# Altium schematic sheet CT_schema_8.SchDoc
size 368 x 245 mm
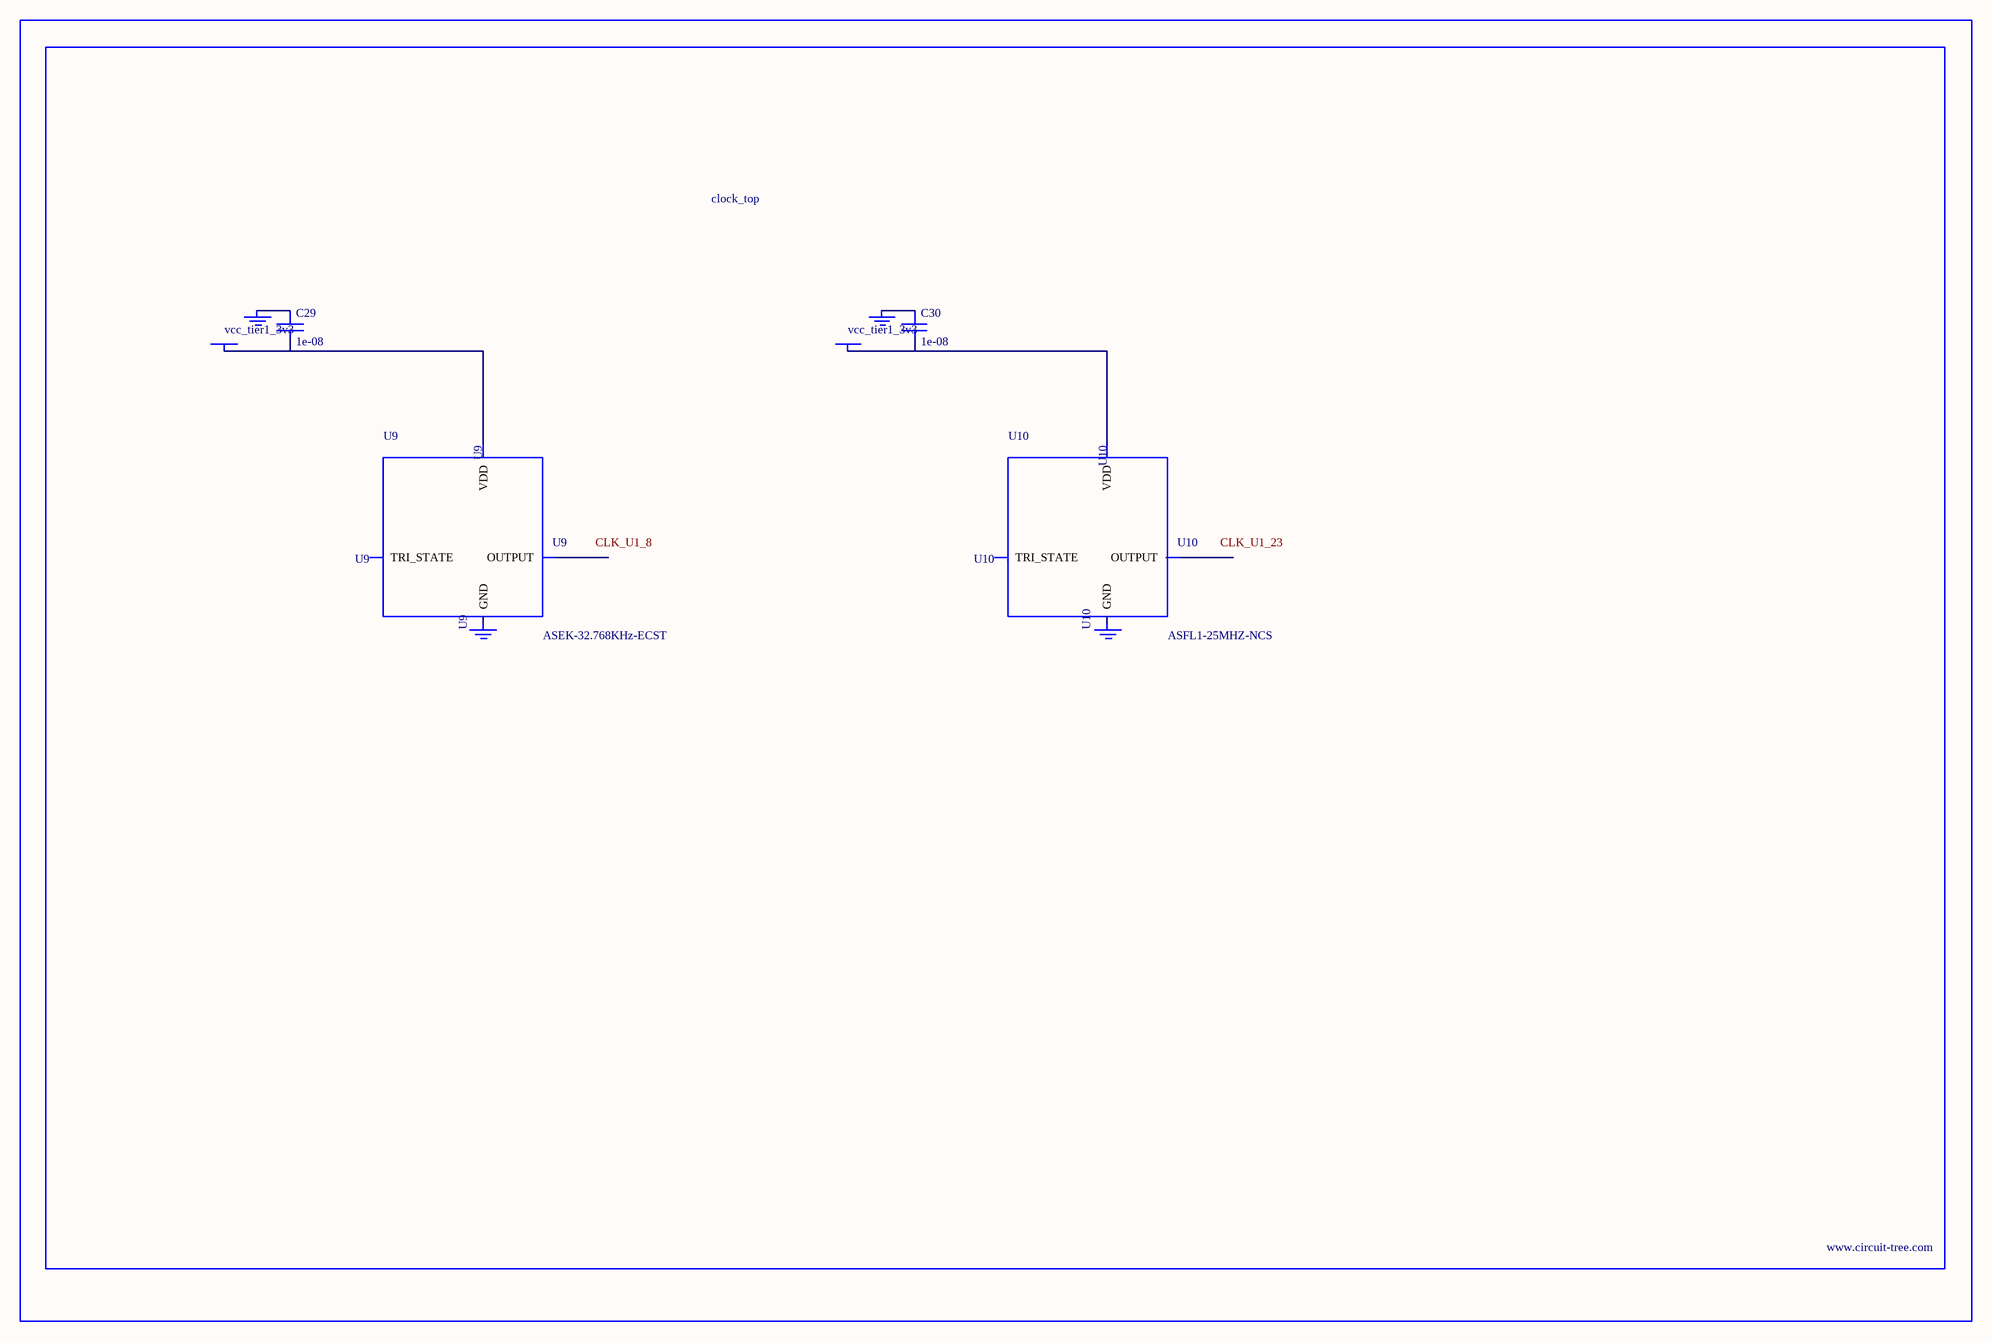
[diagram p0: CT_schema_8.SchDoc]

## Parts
BORDER7  (no value)
C29  1e-08  [C0402]
C30  1e-08  [C0402]
GND_INSTANCE_7_0  (no value)
GND_INSTANCE_7_1  (no value)
GND_INSTANCE_7_2  (no value)
GND_INSTANCE_7_3  (no value)
POWER_INSTANCE_7_0  vcc_tier1_3v3
POWER_INSTANCE_7_1  vcc_tier1_3v3
U9  ASEK-32.768KHz-ECST  [ASEK]
U10  ASFL1-25MHZ-NCS  [ASFL1]

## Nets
NetC29_1: C29.1 GND_INSTANCE_7_0.0(GND)
NetC29_2: C29.2 POWER_INSTANCE_7_0.0(PWR) U9.4(VDD)
NetC30_1: C30.1 GND_INSTANCE_7_2.0(GND)
NetC30_2: C30.2 POWER_INSTANCE_7_1.0(PWR) U10.4(VDD)

Not connected (* = marked no-connect by the designer): GND_INSTANCE_7_1 0(GND); GND_INSTANCE_7_3 0(GND); U9 1(TRI_STATE) 2(GND) 3(OUTPUT); U10 1(TRI_STATE) 2(GND) 3(OUTPUT)

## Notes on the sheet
- Labels drawn without touching a wire or pin: CLK_U1_8, CLK_U1_23

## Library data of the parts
BORDER7 = BORDER_PAGE7
C29 C30 = C0402C103K3RAC
GND_INSTANCE_7_0-GND_INSTANCE_7_3 = GND
POWER_INSTANCE_7_0 POWER_INSTANCE_7_1 = PWR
